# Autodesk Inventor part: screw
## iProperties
Created: 2005-11
Part Number: screw
Document SubType Name: Modeling
Designer: Administrator
Manufacturer: Standard
Standards Organization: Custom
Author: Administrator
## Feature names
1. Revolution1
2. Chamfer1
3. Fillet1
4. Chamfer2
5. Chamfer3
6. Chamfer4
7. Fillet2
8. Extrusion2
9. Chamfer9
10. Chamfer10
